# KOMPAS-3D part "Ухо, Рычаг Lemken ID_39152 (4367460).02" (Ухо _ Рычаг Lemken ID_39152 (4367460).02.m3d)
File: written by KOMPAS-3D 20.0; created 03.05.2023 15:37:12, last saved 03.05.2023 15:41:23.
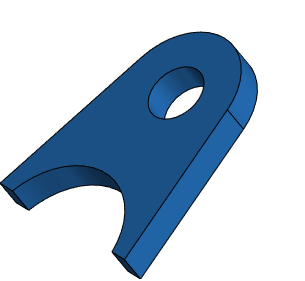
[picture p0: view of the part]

Document properties: Автор: factory; Полное имя файла: C:\Users\factory\Desktop\Чертежи\Рычаг Lemken ID_39152 (4367460)\Ухо _ Рычаг Lemken ID_39152 (4367460).02.m3d

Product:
- Part/product: Ухо  | designation Рычаг Lemken ID_39152 (4367460).02
    Материал: Лист$d16х1400х6000 ГОСТ 19903-2015;295-09Г2-ГС ГОСТ 19281-2014$ (density 7850 kg/m3)
    Масса: 0.803282
    source file: Ухо _ Рычаг Lemken ID_39152 (4367460).02_Чертёж.cdw

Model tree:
1. Эскиз:1
2. Элемент выдавливания:1
     Расстояние 1 = 16

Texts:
  Рычаг Lemken ID_39152 (4367460).02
